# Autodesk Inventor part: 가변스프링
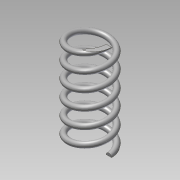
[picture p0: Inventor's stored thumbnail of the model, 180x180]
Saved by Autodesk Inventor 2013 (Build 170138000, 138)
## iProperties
Created: 2020-02
Part Number: 가변스프링
Material: 강철
Document SubType Name: Modeling
Designer: Administrator
Density: 7.85 g/cm^3
Mass: 6.43046 g
Surface Area: 16.6083 cm^2
Volume: 0.819167 cm^3
Author: Administrator
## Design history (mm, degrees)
sketch "스케치1"
  geometry: L1 (0, 0)-(7, 0); L2 (7, 0)-(7, -35.5); L3 (7, -35.5)-(0, -35.5); L4 (0, -35.5)-(0, 0); C1 r 1 at (7, 0)
  constraints: 8 end point, 2 parallel, 1 centre point, 1 coincident, 1 horizontal, 1 perpendicular
  dimensions: "d0" = 2 diameter of C1; "d2" = 35.5 distance of L1.end L2.end (derived); "d3" = 14 diameter of L2 L4
feature "코일1" sketch "스케치1" pitch "d4" = 10; turns "d6" = 6; dims "d5" = 35.5 (= d2), "d7" = 0, angle "d8" = 90 deg, angle "d9" = 90 deg, "d10" = 0, "d11" = 0
sketch "스케치2"
  geometry: L1 (-35.5, 10)-(0, 10); L2 (0, 10)-(0, -10); L3 (0, -10)-(-35.5, -10); L4 (-35.5, -10)-(-35.5, 10); 2 further points
  constraints: 8 end point, 2 parallel, 1 coincident, 1 horizontal, 1 midpoint, 1 perpendicular
  dimensions: "d12" = 35.5 distance of L2.end L3.end (derived); "d14" = 20 distance of L3.end L1.start
extrude "돌출1" sketch "스케치2" stored distance "d15" = 20; taper "d16" = 0 deg
node "솔리드1"
